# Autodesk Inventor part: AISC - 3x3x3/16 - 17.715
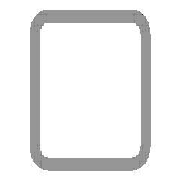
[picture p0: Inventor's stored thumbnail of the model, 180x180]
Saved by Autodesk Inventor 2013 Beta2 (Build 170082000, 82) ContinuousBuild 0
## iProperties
_CCFamilyMember: 9
_CCFamilyDisplayName: ANSI AISC (Square) - Tube
_FrameMemberDoc: Frame Member File
_Version: 15.0.0
_GetPNFromCC: 1
Created: 2011-01
Part Number: AISC - 3x3x3/16 - 17.715
Material: Steel, Mild
Description: Tube
Document SubType Name: Modeling
Standard: ANSI
Designer: Beta-8540w
Standards Organization: ANSI
Language: en-US
Size Designation: 3x3x3/16
Categories: <MemberInstance><Categories><Category DisplayName="Structural Shapes" InternalName="089c4875-fa83-4c05-b084-43b9cc11f5ed" Mnemonic="GRDR"><CategoryParameter Dis
Stock Number: 3x3x3/16
Density: 7.86 g/cm^3
IsCustomPart: 1
G_L: 17.715 in
G_W: 3.000 in
G_H: 3.000 in
Author: Beta-8540w
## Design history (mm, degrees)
node "Start plane"
node "End plane"
sketch "Sketch"
  geometry: L1 (-38.1, -28.575)-(-38.1, 28.575); L2 (-28.575, 38.1)-(28.575, 38.1); L3 (38.1, 28.575)-(38.1, -28.575); L4 (28.575, -38.1)-(-28.575, -38.1); L5 (-28.575, 33.337)-(28.575, 33.338); L6 (33.338, 28.575)-(33.338, -28.575); L7 (28.575, -33.337)-(-28.575, -33.338); L8 (-33.338, -28.575)-(-33.338, 28.575); L9 (0, 56.102)-(0, -56.102) reference; L10 (-56.102, 0)-(56.102, 0) reference; A1 r 9.525 centre (-28.575, -28.575) between (-38.1, -28.575) and (-28.575, -38.1); A2 r 9.525 centre (-28.575, 28.575) between (-28.575, 38.1) and (-38.1, 28.575); A3 r 9.525 centre (28.575, 28.575) between (38.1, 28.575) and (28.575, 38.1); A4 r 9.525 centre (28.575, -28.575) between (28.575, -38.1) and (38.1, -28.575); A5 r 4.763 centre (-28.575, 28.575) between (-28.575, 33.337) and (-33.338, 28.575); A6 r 4.763 centre (28.575, 28.575) between (33.338, 28.575) and (28.575, 33.338); A7 r 4.763 centre (28.575, -28.575) between (28.575, -33.337) and (33.338, -28.575); A8 r 4.763 centre (-28.575, -28.575) between (-33.338, -28.575) and (-28.575, -33.338)
  constraints: 16 end point, 16 point on circle, 8 centre point, 8 tangent, 4 parallel, 3 equal radius, 2 perpendicular, 7 other
  dimensions: "d10" = 76.2 distance between parallel lines of L2 L4 (= G_H); "d11" = 76.2 distance between parallel lines of L1 L3 (= G_W); "d12" = 4.7625 distance between parallel lines of L3 L6 (= G_T); "d15" = 38.1 distance between parallel lines of L2 L10 (= 0.5 x d10); "d16" = 38.1 distance between parallel lines of L9 L3 (= 0.5 x d11); "d17" = 9.525 radius of A1 (= G_IR)
extrude "Body" new body sketch "Sketch" stored distance "d3" = 449.97309 (= G_L); taper "d4" = 0 deg
node "Driven Length"
  sketch "Sketch3"
    geometry: L1 (0, 0)-(10, 0) reference
    constraints: 2 end point, 1 horizontal
  workplane "Work Plane3"
  sketch "Sketch4"
    geometry: L1 (-2, 0)-(12, 0) reference; L2 (-2, 449.973)-(12, 449.973) reference
    dimensions: "d19" = 449.97309 distance between parallel lines of L1 L2 (derived)
body "Solid1"
other parameters: "G_W" = 76.2 [user parameter; used in 1 equation term], "G_H" = 76.2 [user parameter; used in 1 equation term], "G_T" = 4.7625 [user parameter; used in 1 equation term], "G_IR" = 9.525 [user parameter; used in 1 equation term], "G_L" = 449.97309 (= d19) [user parameter; used in 1 equation term], "G_OFFSET_START" = 0 [user parameter; used in 1 equation term], "G_OFFSET_END" = 0 [user parameter; used in 1 equation term], "d13" = 0 (computed from G_OFFSET_START), "d14" = 449.97309 (= G_OFFSET_END + B_L), "B_L" = 449.97309 [user parameter; used in 1 equation term], "d18" = 90 deg
